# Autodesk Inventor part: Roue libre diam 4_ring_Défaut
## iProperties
Shininess: 64.0
Length Units: 11269
Angle Units: 11279
Time Units: 11290
Mass Units: 11283
Length Display Precision: 3
Angle Display Precision: 2
Compacted: True
Part Number: Roue libre diam 4_ring_Défaut
Document SubType Name: Modeling
Created: 2006-01
Material: Par défaut
Designer: riri
Density: 0.0
Volumn: 0.0
Area: 0.0
PropertySet Name: Model Information
Control State: 0
Master: False
Checked Out: False
Author: riri
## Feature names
1. Base1
